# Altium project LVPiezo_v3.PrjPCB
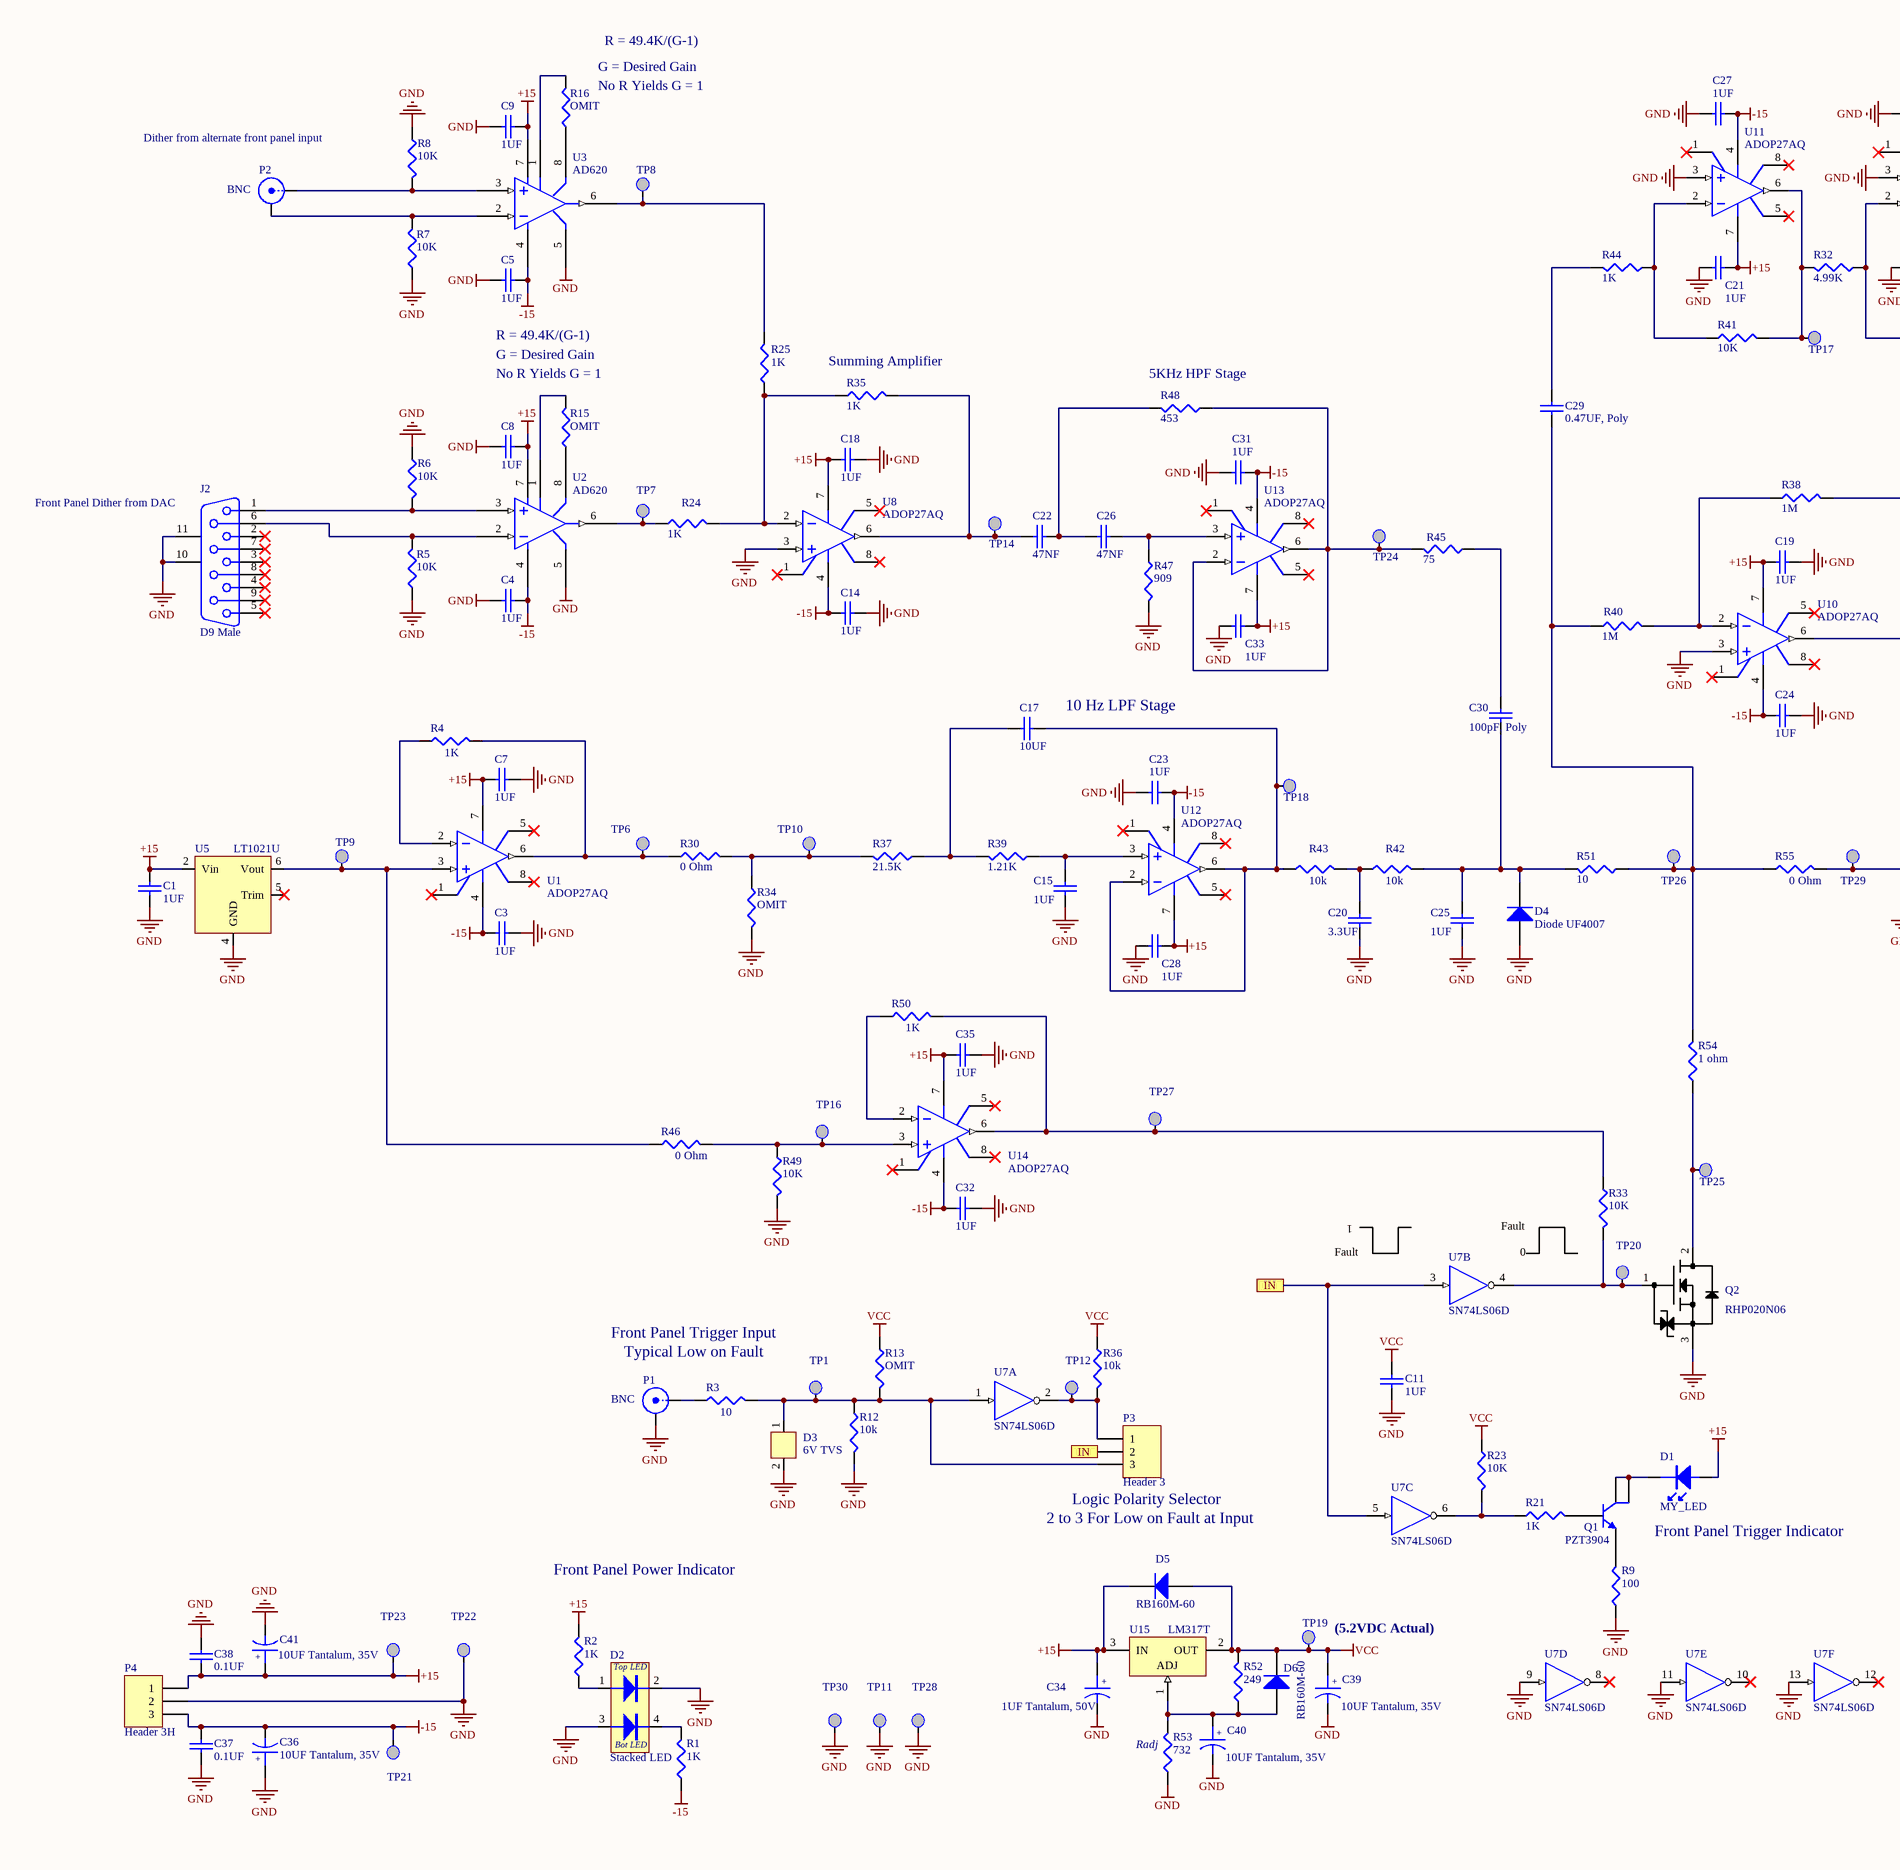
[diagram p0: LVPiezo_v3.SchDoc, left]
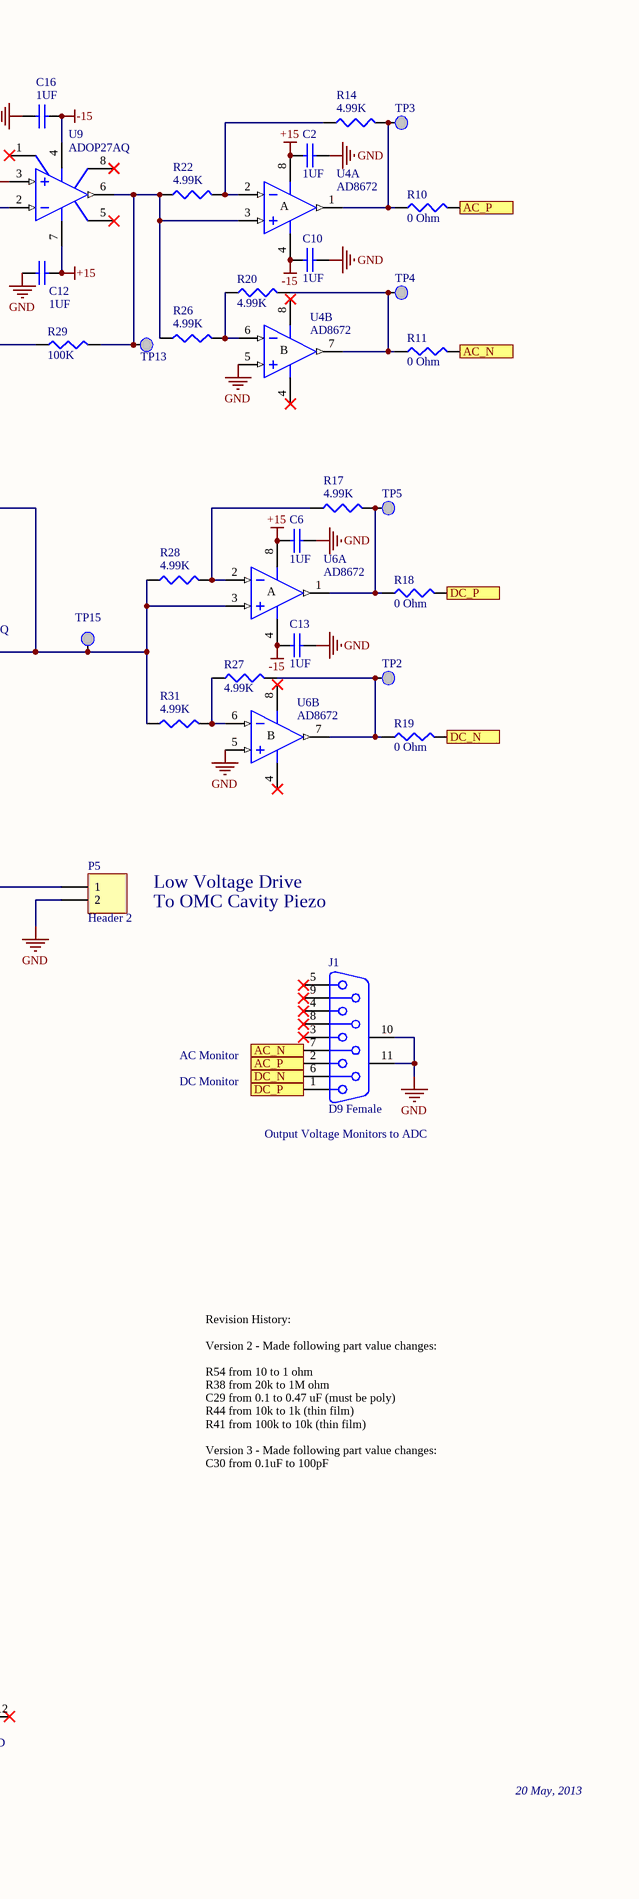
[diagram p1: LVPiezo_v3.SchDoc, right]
1 sheet, 156 parts. Net scope: flat (ports and power ports of the same name join across sheets).
Board file: LV_PiezoDrive_v1.PcbDoc

## Sheet LVPiezo_v3.SchDoc: aLIGO OMC Low Voltage Piezo Drive
size C; Engineer: R.S. Abbott; DocumentNumber: D1300024; Revision: v3; SheetNumber: 1; SheetTotal: 1; PageSetup: Record=PageOptions¦CenterHorizontal=True¦CenterVertical=True¦PrintScale=0.70¦XCorrection=1.00¦YCorrection=1.00¦PrintKind=0¦BorderSize=5000000¦LeftOffset=0¦BottomOffset=0¦Orientation=2¦PaperLength=1000¦PaperWidth=1000¦Scale=100¦PaperSource=7¦PrintQuality=-4¦MediaType=1¦DitherType=10¦PaperKind=11x17¦PrintScaleMode=1

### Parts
C1  1UF  [3216[1206]]
C2  1UF  [3216[1206]]
C3  1UF  [3216[1206]]
C4  1UF  [3216[1206]]
C5  1UF  [3216[1206]]
C6  1UF  [3216[1206]]
C7  1UF  [3216[1206]]
C8  1UF  [3216[1206]]
C9  1UF  [3216[1206]]
C10  1UF  [3216[1206]]
C11  1UF  [3216[1206]]
C12  1UF  [3216[1206]]
C13  1UF  [3216[1206]]
C14  1UF  [3216[1206]]
C15  1UF  [ECQ-E1105KF]
C16  1UF  [3216[1206]]
C17  10UF  [ECQ-E1106KF_Vert]
C18  1UF  [3216[1206]]
C19  1UF  [3216[1206]]
C20  3.3UF  [ECQ-E1335KF]
C21  1UF  [3216[1206]]
C22  47NF  [ECQ-E1473KF]
C23  1UF  [3216[1206]]
C24  1UF  [3216[1206]]
C25  1UF  [ECQ-E1105KF]
C26  47NF  [ECQ-E1473KF]
C27  1UF  [3216[1206]]
C28  1UF  [3216[1206]]
C29  0.47UF, Poly  [ECQ-E1104KF]
C30  100pF, Poly  [ECQ-E1104KF]
C31  1UF  [3216[1206]]
C32  1UF  [3216[1206]]
C33  1UF  [3216[1206]]
C34  1UF Tantalum, 50V  [3216]
C35  1UF  [3216[1206]]
C36  10UF Tantalum, 35V  [7343-31]
C37  0.1UF  [3216[1206]]
C38  0.1UF  [3216[1206]]
C39  10UF Tantalum, 35V  [7343-31]
C40  10UF Tantalum, 35V  [7343-31]
C41  10UF Tantalum, 35V  [7343-31]
D1  MY_LED  [LED_RA]
D2  Stacked LED  [my LUMEX Dual LED]
D3  6V TVS  [DO-214AC (SMA)]
D4  Diode UF4007  [DO-41]
D5  RB160M-60  [SOD123]
D6  RB160M-60  [SOD123]
J1  D9 Female  [MY_DB9F_RA]
J2  D9 Male  [MY_DB9M_RA]
P1  BNC  [BNC_RA CON]
P2  BNC  [BNC_RA CON]
P3  Header 3  [HDR1X3]
P4  Header 3H  [Molex_156_RA_3]
P5  Header 2  [MOLEX_156_RA_2]
Q1  PZT3904  [SOT-223]
Q2  RHP020N06  [SOT89M]
R1  1K  [3216[1206]]
R2  1K  [3216[1206]]
R3  10  [3216[1206]]
R4  1K  [3216[1206]]
R5  10K  [3216[1206]]
R6  10K  [3216[1206]]
R7  10K  [3216[1206]]
R8  10K  [3216[1206]]
R9  100  [3216[1206]]
R10  0 Ohm  [3216[1206]]
R11  0 Ohm  [3216[1206]]
R12  10k  [3216[1206]]
R13  OMIT  [3216[1206]]
R14  4.99K  [3216[1206]]
R15  OMIT  [3216[1206]]
R16  OMIT  [3216[1206]]
R17  4.99K  [3216[1206]]
R18  0 Ohm  [3216[1206]]
R19  0 Ohm  [3216[1206]]
R20  4.99K  [3216[1206]]
R21  1K  [3216[1206]]
R22  4.99K  [3216[1206]]
R23  10K  [3216[1206]]
R24  1K  [3216[1206]]
R25  1K  [3216[1206]]
R26  4.99K  [3216[1206]]
R27  4.99K  [3216[1206]]
R28  4.99K  [3216[1206]]
R29  100K  [3216[1206]]
R30  0 Ohm  [3216[1206]]
R31  4.99K  [3216[1206]]
R32  4.99K  [3216[1206]]
R33  10K  [3216[1206]]
R34  OMIT  [3216[1206]]
R35  1K  [3216[1206]]
R36  10k  [3216[1206]]
R37  21.5K  [3216[1206]]
R38  1M  [3216[1206]]
R39  1.21K  [3216[1206]]
R40  1M  [3216[1206]]
R41  10K  [3216[1206]]
R42  10k  [3216[1206]]
R43  10k  [3216[1206]]
R44  1K  [3216[1206]]
R45  75  [3216[1206]]
R46  0 Ohm  [3216[1206]]
R47  909  [3216[1206]]
R48  453  [3216[1206]]
R49  10K  [3216[1206]]
R50  1K  [3216[1206]]
R51  10  [3216[1206]]
R52  249  [3216[1206]]
R53  732  [3216[1206]]
R54  1 ohm  [3216[1206]]
R55  0 Ohm  [3216[1206]]
TP1  TESTPT  [smt_tp]  (value not drawn)
TP2  TESTPT  [smt_tp]  (value not drawn)
TP3  TESTPT  [smt_tp]  (value not drawn)
TP4  TESTPT  [smt_tp]  (value not drawn)
TP5  TESTPT  [smt_tp]  (value not drawn)
TP6  TESTPT  [smt_tp]  (value not drawn)
TP7  TESTPT  [smt_tp]  (value not drawn)
TP8  TESTPT  [smt_tp]  (value not drawn)
TP9  TESTPT  [smt_tp]  (value not drawn)
TP10  TESTPT  [smt_tp]  (value not drawn)
TP11  TESTPT  [smt_tp]  (value not drawn)
TP12  TESTPT  [smt_tp]  (value not drawn)
TP13  TESTPT  [smt_tp]  (value not drawn)
TP14  TESTPT  [smt_tp]  (value not drawn)
TP15  TESTPT  [smt_tp]  (value not drawn)
TP16  TESTPT  [smt_tp]  (value not drawn)
TP17  TESTPT  [smt_tp]  (value not drawn)
TP18  TESTPT  [smt_tp]  (value not drawn)
TP19  TESTPT  [smt_tp]  (value not drawn)
TP20  TESTPT  [smt_tp]  (value not drawn)
TP21  TESTPT  [smt_tp]  (value not drawn)
TP22  TESTPT  [smt_tp]  (value not drawn)
TP23  TESTPT  [smt_tp]  (value not drawn)
TP24  TESTPT  [smt_tp]  (value not drawn)
TP25  TESTPT  [smt_tp]  (value not drawn)
TP26  TESTPT  [smt_tp]  (value not drawn)
TP27  TESTPT  [smt_tp]  (value not drawn)
TP28  TESTPT  [smt_tp]  (value not drawn)
TP29  TESTPT  [smt_tp]  (value not drawn)
TP30  TESTPT  [smt_tp]  (value not drawn)
U1  ADOP27AQ  [SO8_M]
U2  AD620  [SO8_M]
U3  AD620  [SO8_M]
U4  AD8672  [so8_m]  (parts A,B of 2)
U5  LT1021U  [SO8_M]
U6  AD8672  [so8_m]  (parts A,B of 2)
U7  SN74LS06D  [D014_N]  (parts A,B,C,D,E,F of 6)
U8  ADOP27AQ  [SO8_M]
U9  ADOP27AQ  [SO8_M]
U10  ADOP27AQ  [SO8_M]
U11  ADOP27AQ  [SO8_M]
U12  ADOP27AQ  [SO8_M]
U13  ADOP27AQ  [SO8_M]
U14  ADOP27AQ  [SO8_M]
U15  LM317T  [MY_TO220]

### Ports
AC_N, AC_P, DC_N, DC_P, IN

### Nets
+15: C1.1 C2.2 C6.2 C7.2 C8.1 C9.1 C12.2 C18.2 C19.2 C21.2 C28.2 C33.2 C34.1 C35.2 C38.1 C41.1 D1.A D5.2(K) P4.1 R2.2 TP23.1 U1.7(V+) U2.7(+Vs) U3.7(+Vs) U4.8(V+) U5.2(Vin) U6.8(V+) U8.7(V+) U9.7(V+) U10.7(V+) U11.7(V+) U12.7(V+) U13.7(V+) U14.7(V+) U15.3(IN)
-15: C3.2 C4.1 C5.1 C10.2 C13.2 C14.2 C16.2 C23.2 C24.2 C27.2 C31.2 C32.2 C36.2 C37.1 P4.3 R1.1 TP21.1 U1.4(V-) U2.4(-Vs) U3.4(-Vs) U4.4(V-) U6.4(V-) U8.4(V-) U9.4(V-) U10.4(V-) U11.4(V-) U12.4(V-) U13.4(V-) U14.4(V-)
GND: C1.2 C2.1 C3.1 C4.2 C5.2 C6.1 C7.1 C8.2 C9.2 C10.1 C11.2 C12.1 C13.1 C14.1 C15.2 C16.1 C18.1 C19.1 C20.2 C21.1 C23.1 C24.1 C25.2 C27.1 C28.1 C31.1 C32.1 C33.1 C34.2 C35.1 C36.1 C37.2 C38.2 C39.2 C40.2 C41.2 D2.2(CATHODE) D2.3(ANODE) D3.2(b) D4.1(A) J1.10(MH1) J1.11(MH2) J2.10(MH1) J2.11(MH2) P1.2(Y) P4.2 P5.2 Q2.3(S) R5.1 R6.1 R7.1 R8.1 R9.1 R12.2 R34.2 R47.2 R49.2 R53.1 TP11.1 TP22.1 TP28.1 TP30.1 U2.5(REF) U3.5(REF) U4.5(IN+) U5.4(GND) U6.5(IN+) U7.7(GND) U7.9(A) U7.11(A) U7.13(A) U8.3(IN+) U9.3(IN+) U10.3(IN+) U11.3(IN+)
VCC: C11.1 C39.1 D5.1(A) D6.2(K) R13.1 R23.1 R36.1 R52.2 TP19.1 U7.14(VCC) U15.2(OUT)
NetC15_1: C15.1 R39.1 U12.3(IN+)
NetC17_1: C17.1 R37.1 R39.2
NetC17_2: C17.2 R43.1 TP18.1 U12.2(IN-) U12.6(OUT)
NetC20_1: C20.1 R42.1 R43.2
NetC22_1: C22.1 R35.2 TP14.1 U8.6(OUT)
NetC22_2: C22.2 C26.1 R48.2
NetC25_1: C25.1 C30.2 D4.2(K) R42.2 R51.2
NetC26_2: C26.2 R47.1 U13.3(IN+)
NetC29_1: C29.1 R40.1 R51.1 R54.2 R55.1 TP26.1
NetC29_2: C29.2 R44.2
NetC30_1: C30.1 R45.1
NetC40_1: C40.1 D6.1(A) R52.1 R53.2 U15.1(ADJ)
NetD1_K: D1.K Q1.2(C) Q1.4(C)
NetD2_1: D2.1(COM) R2.1
NetD2_4: D2.4(ANODE) R1.2
NetD3_1: D3.1(a) P3.3 R3.2 R12.1 R13.2 TP1.1 U7.1(A)
NetJ1_1: J1.1 R18.2 ; port DC_P
NetJ1_2: J1.2 R10.2 ; port AC_P
NetJ1_6: J1.6 R19.2 ; port DC_N
NetJ1_7: J1.7 R11.2 ; port AC_N
NetJ2_1: J2.1 R6.2 U2.3(+IN)
NetJ2_6: J2.6 R5.2 U2.2(-IN)
NetP1_1: P1.1(X) R3.1
NetP2_1: P2.1(X) R8.2 U3.3(+IN)
NetP2_2: P2.2(Y) R7.2 U3.2(-IN)
NetP3_1: P3.1 R36.2 TP12.1 U7.2(Y)
NetP3_2: P3.2 U7.3(A) U7.5(A) ; port IN
NetP5_1: P5.1 R55.2 TP29.1
NetQ1_1: Q1.1(B) R21.2
NetQ1_3: Q1.3(E) R9.2
NetQ2_1: Q2.1(G) R33.2 TP20.1 U7.4(Y)
NetQ2_2: Q2.2(D) R54.1 TP25.1
NetR4_1: R4.1 U1.2(IN-)
NetR4_2: R4.2 R30.1 TP6.1 U1.6(OUT)
NetR10_1: R10.1 R14.2 TP3.1 U4.1(OUT)
NetR11_1: R11.1 R20.2 TP4.1 U4.7(OUT)
NetR14_1: R14.1 R22.2 U4.2(IN-)
NetR15_1: R15.1 U2.8(RG)
NetR15_2: R15.2 U2.1(RG*)
NetR16_1: R16.1 U3.8(RG)
NetR16_2: R16.2 U3.1(RG*)
NetR17_1: R17.1 R28.2 U6.2(IN-)
NetR17_2: R17.2 R18.1 TP5.1 U6.1(OUT)
NetR19_1: R19.1 R27.2 TP2.1 U6.7(OUT)
NetR20_1: R20.1 R26.2 U4.6(IN-)
NetR21_1: R21.1 R23.2 U7.6(Y)
NetR22_1: R22.1 R26.1 R29.2 TP13.1 U4.3(IN+) U9.6(OUT)
NetR24_1: R24.1 TP7.1 U2.6(OUT)
NetR24_2: R24.2 R25.1 R35.1 U8.2(IN-)
NetR25_2: R25.2 TP8.1 U3.6(OUT)
NetR27_1: R27.1 R31.2 U6.6(IN-)
NetR28_1: R28.1 R31.1 R38.2 TP15.1 U6.3(IN+) U10.6(OUT)
NetR29_1: R29.1 R32.1 U9.2(IN-)
NetR30_2: R30.2 R34.1 R37.2 TP10.1
NetR32_2: R32.2 R41.2 TP17.1 U11.6(OUT)
NetR33_1: R33.1 R50.2 TP27.1 U14.6(OUT)
NetR38_1: R38.1 R40.2 U10.2(IN-)
NetR41_1: R41.1 R44.1 U11.2(IN-)
NetR45_2: R45.2 R48.1 TP24.1 U13.2(IN-) U13.6(OUT)
NetR46_1: R46.1 TP9.1 U1.3(IN+) U5.6(Vout)
NetR46_2: R46.2 R49.1 TP16.1 U14.3(IN+)
NetR50_1: R50.1 U14.2(IN-)

Not connected (* = marked no-connect by the designer): J1 3* 4* 5* 8* 9*; J2 2* 3* 4* 5* 7* 8* 9*; U1 1(NULL1)* 5(NC)* 8(NULL2)*; U5 5(Trim)*; U7 8(Y)* 10(Y)* 12(Y)*; U8 1(NULL1)* 5(NC)* 8(NULL2)*; U9 1(NULL1)* 5(NC)* 8(NULL2)*; U10 1(NULL1)* 5(NC)* 8(NULL2)*; U11 1(NULL1)* 5(NC)* 8(NULL2)*; U12 1(NULL1)* 5(NC)* 8(NULL2)*; U13 1(NULL1)* 5(NC)* 8(NULL2)*; U14 1(NULL1)* 5(NC)* 8(NULL2)*

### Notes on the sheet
- R = 49.4K/(G-1)
- (near R16) G = Desired Gain
- (near R16) No R Yields G = 1
- Dither from alternate front panel input
- G = Desired Gain
- (near R35) Summing Amplifier
- (near R15) No R Yields G = 1
- (near R48) 5KHz HPF Stage
- (near J2) Front Panel Dither from DAC
- (near C17) 10 Hz LPF Stage
- Low Voltage Drive
- To OMC Cavity Piezo
- DC Monitor
- AC Monitor
- (near J1) Output Voltage Monitors to ADC
- Fault
- 1
- (near U7) 0
- Front Panel Trigger Input
- Typical Low on Fault
- 2 to 3 For Low on Fault at Input
- (near P3) Logic Polarity Selector
- Front Panel Power Indicator
- (near Q1) Front Panel Trigger Indicator
- (5.2VDC Actual)
- Revision History:
  Version 2 - Made following part value changes:
  R54 from 10 to 1 ohm
  R38 from 20k to 1M ohm
  C29 from 0.1 to 0.47 uF (must be poly)
  R44 from 10k to 1k (thin film)
  R41 from 100k to 10k (thin film)
  Version 3 - Made following part value changes:
  C30 from 0.1uF to 100pF
- (near R53) Radj
- 20 May, 2013

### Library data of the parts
C1-C29 C31-C33 C35 C37 C38 = MYCAP: Checked: y
C30 = MYCAP: Manufacturer: KEMET; Manufacturer Part Number: PFR5101J100J11L4BULK; Dielectric Material: PP; Tolerance: 5%; Voltage Rating (AC): 63V; Voltage Rating (DC): 100V; Lead Diameter: 0.5mm
C34 C36 C39-C41 = CAPACITOR POL: Polarized Cap; Checked: y
D1 = MY_LED: Checked: y
D2 = Dual Stacked LED: Dual Green LED; Checked: y
D3 = TVS: 5V Bi-directional Transient Voltage Suppressor; Checked: y
D4 = Diode 1N4001: 1 Amp General Purpose Rectifier; Checked: y
D5 D6 = Diode 1N4148: High Conductance Fast Diode; Checked: y
J1 J2 = D Connector 9: Receptacle Assembly, 9 Position, Right Angle; Checked: y
P1 P2 = BNC: BNC Elbow Connector; Checked: y
P3 = Header 3: Header, 3-Pin; Checked: y
P4 = Header 3H: Header, 3-Pin, Right Angle; Checked: y
P5 = Header 2: Header, 2-Pin; Checked: y
Q1 = PZT3904: NPN General Purpose Amplifier; Checked: y
Q2 = RHP020N06: N-Channel, Enh Mode, MOSFET; Checked: y
R1 R2 R10-R14 R17-R20 R22-R28 R30 R31 R33-R36 R38 R40 R49 = Res3: Resistor; Checked: y
R3-R9 R15 R16 R21 R29 R32 R37 R39 R41-R48 R50-R55 = MYRES: Checked: y
TP1-TP30 = TESTPT: PCB Testpoint; Checked: y
U1 U8-U14 = ADOP27AQ: Ultra-Low Noise, Precision Operational Amplifier; Checked: y
U2 U3 = AD620: Low power instrumentation amplifier; Checked: y
U4 U6 = AD826AR: High-Speed, Low-Power Dual Operational Amplifier; Checked: y
U5 = LT1021: Checked: y
U7 = SN74LS06D: Hex Inverter Buffer / Driver with Open-Collector High-Voltage Outputs; Checked: y
U15 = LM317T: Three-Terminal Adjustable Output Positive Voltage Regulator; Checked: y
